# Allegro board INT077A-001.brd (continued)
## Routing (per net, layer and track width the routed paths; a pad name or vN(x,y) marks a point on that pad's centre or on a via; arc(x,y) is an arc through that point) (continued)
SCL_PD: length 2.8
  TOP w0.305: R47.2 99.03,62.23 98.2,63.07 SW2.12
SCL_PUP: length 2.2
  TOP w0.305: SW1.14 v1(95.81,52.91)
  BOTTOM w0.305: R4.1 v1(95.81,52.91)
SCL_SMBCLK: length 85.6
  TOP w0.305: J13.1 106.12,62.99 106.12,65.48 U2.6 94.03,74.37 92.79,73.13 92.79,53.95 91.72,52.88 90.55,52.88 90.53,52.91 SW1.3 88.7,52.91 88.67,52.88 78.49,52.88 75.15,49.55 U1.38 ; SW2.5 v1(90.78,63.07)
  BOTTOM w0.305: v1(90.78,63.07) 91.72,63.07 93.12,64.47 93.12,72.62 94.87,74.37 U2.6
SDA_PD: length 3
  TOP w0.305: SW2.11 98.15,61.8 98.69,61.25 99.14,61.25 99.69,60.7 R46.2
SDA_PUP: length 2.4
  TOP w0.305: SW1.13 v1(95.78,51.64)
  BOTTOM w0.305: R5.1 96.16,51.26 v1(95.78,51.64)
SDA_SMBDAT: length 85.3
  TOP w0.305: SW2.6 v1(90.88,61.8) ; U1.37 75.72,49.05 78.33,51.66 88.67,51.66 88.7,51.64 SW1.4 92.84,51.64 93.78,52.58 93.78,70.48 95.07,71.78 96.14,71.78 96.19,71.83 U2.5 ; J13.3 111.2,61.47 111.18,61.49 111.18,64.21 103.56,71.83 v1(101.85,71.83)
  BOTTOM w0.305: v1(101.85,71.83) U2.5 96.19,71.83 94.36,70 94.36,62.53 93.62,61.8 v1(90.88,61.8)
SMBUSZ: length 22.5
  TOP w0.305: U1.39 74.56,50.05 78.69,54.18 SW1.2
SMBUSZ_PD: length 2.1
  TOP w0.305: SW1.15 v1(95.91,54.18)
  BOTTOM w0.305: v1(95.91,54.18) 96.29,54.56 R24.2
TEST_PUP: length 2.6
  TOP w0.305: SW1.16 v1(95.78,55.45)
  BOTTOM w0.305: R22.1 96.55,56.21 v1(95.78,55.45)
TEST_TRSTZ: length 98.5
  TOP w0.305: v1(90.68,55.5) 89.66,55.5 SW1.1 89.59,55.42 v1(88.47,55.42) ; U1.49 67.25,56.36 67.66,56.77 v1(67.72,56.77)
  BOTTOM w0.305: v1(67.72,56.77) 84.56,56.77 85.9,55.42 v1(88.47,55.42) ; JP6.1 84.1,92.56 82.88,92.56 82.09,93.34 82.09,96.09 82.93,96.93 95.81,96.93 100.3,92.43 100.3,80.95 103.23,78.03 103.23,59.26 101.52,57.56 94.18,57.56 92.13,55.5 v1(90.68,55.5)
USB_DM_DN1: length 107.3
  TOP w0.229: U1.2 58.06,54.13 56.87,54.13 56.87,54.14 55.64,54.14 53.52,56.26 43.82,56.26 42.7,55.14 14.12,55.14 7.54,48.56 7.54,10.69 9.27,8.97 15.67,8.97 17.61,10.91 17.61,12.9 J4.2
USB_DM_DN2: length 71.3
  TOP w0.229: J3.2 48.09,12.9 48.09,10.5 46.25,8.66 39.67,8.66 37.95,10.39 37.95,43.54 43.01,48.6 51.37,48.6 52.92,50.14 56.54,50.14 56.63,50.05 U1.10
USB_DM_DN3: length 55.1
  TOP w0.229: U1.18 60.17,45.36 60.17,44.17 60.16,44.17 60.16,43.73 57.28,40.85 57.28,28.61 67.01,18.88 67.01,12.25 70.32,8.94 76.11,8.94 78.57,11.4 78.57,12.9 J5.2
USB_DM_DN4: length 78.7
  TOP w0.229: U1.25 63.67,45.36 63.67,44.17 63.67,44.17 63.67,40.04 64.94,38.77 64.94,33.8 71.23,27.51 91.5,27.51 99.36,19.64 99.36,8.93 100.64,7.65 107,7.65 109.05,9.7 109.05,12.9 J2.2
USB_DM_UP: length 40.5
  TOP w0.229: J1.2 65.57,87.2 70.18,87.2 71.91,85.47 71.91,77.72 65.61,71.42 65.61,60.35 64.84,59.58 64.84,57.43 64.83,57.43 64.83,56.24 U1.54
USB_DP_DN1: length 109
  TOP w0.229: U1.1 58.06,54.47 56.87,54.47 56.87,54.47 55.78,54.47 53.65,56.59 43.68,56.59 42.57,55.47 13.99,55.47 7.21,48.7 7.21,10.56 9.13,8.64 15.81,8.64 17.95,10.77 17.95,12.9 J4.3
USB_DP_DN2: length 73
  TOP w0.229: U1.9 56.63,50.55 56.54,50.47 52.78,50.47 51.24,48.93 42.87,48.93 37.62,43.67 37.62,10.25 39.54,8.33 46.39,8.33 48.43,10.37 48.43,12.9 J3.3
USB_DP_DN3: length 56.2
  TOP w0.229: U1.17 59.83,45.36 59.83,44.17 59.83,44.17 59.83,43.87 56.95,40.99 56.95,28.47 66.67,18.75 66.67,12.12 70.18,8.61 76.25,8.61 78.91,11.26 78.91,12.9 J5.3
USB_DP_DN4: length 79.8
  TOP w0.229: U1.24 63.33,45.36 63.33,44.17 63.33,44.17 63.33,39.91 64.61,38.63 64.61,33.66 71.09,27.18 91.36,27.18 99.03,19.51 99.03,8.79 100.51,7.32 107.14,7.32 109.39,9.56 109.39,12.9 J2.3
USB_DP_UP: length 41.1
  TOP w0.229: J1.3 65.56,87.53 70.32,87.53 72.24,85.61 72.24,77.59 65.94,71.29 65.94,60.21 65.17,59.44 65.17,56.24 U1.53
USB_SSRXM_DN1: length 64
  TOP w0.229: U1.7 56.63,51.55 56.54,51.64 51.26,51.64 50.38,50.75 37.96,50.75 20.94,33.74 20.94,18.4 21.62,17.73 21.62,17.27 20.94,16.6 20.94,16.08 J4.5
USB_SSRXM_DN2: length 38.7
  TOP w0.229: U1.15 58.06,47.63 56.87,47.63 56.87,47.64 56.13,47.64 52.63,44.14 52.63,41.33 54.36,39.6 54.36,29.84 51.42,26.91 51.42,18.32 52.1,17.65 52.1,17.21 51.42,16.54 51.42,16.08 J3.5
USB_SSRXM_DN3: length 47.1
  TOP w0.229: J5.5 81.9,16.08 81.9,23.1 79.58,25.43 66.35,25.43 61.75,30.03 61.75,41.2 62.67,42.12 62.67,45.36 U1.23
USB_SSRXM_DN4: length 66.7
  TOP w0.229: J2.5 112.38,16.08 112.38,25.56 105.23,32.72 76.29,32.72 66.17,42.83 66.17,45.36 U1.30
USB_SSRXN_UP: length 40.1
  TOP w0.229: U1.59 62.33,56.24 62.33,57.43 62.34,57.43 62.34,61.95 60.02,64.26 60.02,76.6 55.8,80.81 55.8,86.17 56.68,87.05 59.55,87.05 60.27,86.32 60.27,85.07 J1.8
USB_SSRXP_DN1: length 64
  TOP w0.229: J4.6 20.61,16.08 20.61,33.87 37.83,51.08 50.25,51.08 51.13,51.97 56.54,51.97 56.63,52.05 U1.6
USB_SSRXP_DN2: length 38.7
  TOP w0.229: J3.6 51.09,16.08 51.09,27.05 54.03,29.98 54.03,39.46 52.3,41.19 52.3,44.27 55.99,47.97 58.06,47.97 U1.14
USB_SSRXP_DN3: length 47.1
  TOP w0.229: J5.6 81.57,16.08 81.57,22.96 79.44,25.1 66.22,25.1 61.42,29.9 61.42,41.34 62.34,42.26 62.34,44.17 62.33,44.17 62.33,45.36 U1.22
USB_SSRXP_DN4: length 66.7
  TOP w0.229: U1.29 65.83,45.36 65.83,44.17 65.84,44.17 65.84,42.7 76.15,32.38 105.1,32.38 112.05,25.43 112.05,16.08 J2.6
USB_SSRXP_UP: length 40.1
  TOP w0.229: J1.9 59.54,84.36 59.94,84.77 59.94,86.18 59.41,86.72 59.05,86.72 58.72,86.39 58.72,86.21 58.4,85.88 57.93,85.88 57.61,86.21 57.61,86.39 57.28,86.72 56.82,86.72 56.13,86.03 56.13,80.95 60.35,76.73 60.35,64.4 62.67,62.08 62.67,56.24 U1.58
USB_SSTXM_DN1: length 64.1
  TOP w0.229: C52.2 14.94,22.13 14.94,34.14 33.93,53.14 44.09,53.14 44.98,54.03 53.44,54.03 54.33,53.14 56.87,53.14 56.87,53.13 58.06,53.13 U1.4
USB_SSTXM_DN2: length 38.1
  TOP w0.229: U1.12 58.06,49.13 56.87,49.13 56.87,49.14 54.89,49.14 52.36,46.61 48.97,46.61 43.36,41 43.36,34.62 45.42,32.56 45.42,22.13 C43.2
USB_SSTXM_DN3: length 36.5
  TOP w0.229: U1.20 61.17,45.36 61.17,43.94 61.16,43.93 61.16,42.52 59.69,41.05 59.69,29.27 65.62,23.34 75.23,23.34 76.05,22.53 C53.2
USB_SSTXM_DN4: length 57.2
  TOP w0.229: U1.27 64.67,45.36 64.67,41.73 67.82,38.58 67.82,35.01 72.7,30.12 100.59,30.12 106.38,24.34 106.38,22.13 C42.2
USB_SSTXM_UP: length 22.8
  TOP w0.229: U1.56 63.75,57.75 63.84,57.83 63.84,60.02 63.5,60.35 63.5,73.08 66.46,76.04 66.46,77.37 C36.2
USB_SSTXP_DN1: length 64.6
  TOP w0.229: U1.3 58.06,53.47 54.47,53.47 53.58,54.36 44.85,54.36 43.96,53.47 33.8,53.47 14.61,34.28 14.61,22.13 C54.2
USB_SSTXP_DN2: length 38.7
  TOP w0.229: C45.2 45.09,22.13 45.09,32.42 43.03,34.48 43.03,41.13 48.83,46.94 52.22,46.94 54.75,49.47 58.06,49.47 U1.11
USB_SSTXP_DN3: length 36.5
  TOP w0.229: C55.2 75.58,22.13 75.58,22.53 75.1,23.01 65.48,23.01 59.36,29.13 59.36,41.18 60.83,42.66 60.83,44.07 60.84,44.07 60.84,44.17 60.83,44.17 60.83,45.36 U1.19
USB_SSTXP_DN4: length 57.2
  TOP w0.229: C44.2 106.05,22.13 106.05,24.21 100.46,29.79 72.57,29.79 67.49,34.87 67.49,38.45 64.34,41.6 64.34,44.17 64.33,44.17 64.33,45.36 U1.26
USB_SSTXP_UP: length 22.8
  TOP w0.229: U1.55 64.25,57.75 64.17,57.83 64.17,60.15 63.83,60.49 63.83,72.94 66.79,75.9 66.79,77.37 C37.2
USB_VBUS_UP: length 8.7
  TOP w0.305: D1.1 v1(48.92,85.22) ; C35.1 v1(51.74,85.04)
  L3_VCC w0.305: J1.1 63.24,86.36 ; J1.1 62.23,85.35 ; J1.1 61.22,86.36 ; J8.2 77.85,81.03 ; J8.2 76.78,79.96 ; J8.2 77.85,78.89
N17052812: length 25
  TOP w0.305: U1.48 68.85,56.33 69.34,56.82 69.34,66.6 73.91,71.17 R3.1 R2.1
N17181221: length 4.6
  TOP w0.305: R14.1 99.82,75.93 99.82,75.93 R10.2 U2.7
N17181233: length 2.6
  TOP w0.305: R11.2 87.66,79.48 87.68,79.45 U2.1
N17181243: length 2.6
  TOP w0.305: U2.2 87.68,76.91 87.66,76.94 R12.2
N17181324: length 2.6
  TOP w0.305: U2.3 87.68,74.37 87.66,74.4 R13.2
N17381185: length 1.8
  TOP w0.305: v1(17.98,24.38) D5.2
  BOTTOM w0.305: R30.1 v1(17.98,24.38)
N17383170: length 2.1
  TOP w0.305: D1.2 R16.1
N17408350: length 2.4
  TOP w0.305: D4.2 R28.1
N18334081: length 11.6
  TOP w0.305: U1.62 60.75,57.59 v1(60.48,57.86)
  BOTTOM w0.305: Y1.3 58.03,64.58 57.71,64.26 57.71,60.68 57.99,60.4 C2.1 59.08,60.25 59.08,59.69 60.07,58.7 R1.2 60.48,58.57 v1(60.48,57.86)
N18334093: length 7.4
  TOP w0.305: v1(61.54,57.86) 61.25,57.57 U1.61
  BOTTOM w0.305: v1(61.54,57.86) 61.54,58.6 R1.1 62.61,58.7 63.14,59.23 63.14,59.65 63.17,59.67 C1.1 Y1.1
N18711690: length 2
  TOP w0.305: D6.2 48.26,23.46 v1(48.26,24.36)
  BOTTOM w0.305: R31.1 v1(48.26,24.36)
N18712170: length 2.1
  TOP w0.305: v1(79.81,23.29) 78.87,23.29 D7.2
  BOTTOM w0.305: R35.1 78.88,22.95 79.46,22.95 v1(79.81,23.29)
N18712674: length 1.9
  TOP w0.305: D8.2 v1(109.5,24.31)
  BOTTOM w0.305: v1(109.5,24.31) R37.1
N18713919: length 1.9
  TOP w0.305: U1.64 v1(59.24,56.15)
  BOTTOM w0.305: R21.2 58.36,56.92 58.79,56.5 58.89,56.5 v1(59.24,56.15)
N18725733: length 2.6
  TOP w0.305: R2.2 J8.1
N18726136: length 10.4
  BOTTOM w1.016: J7.1 86.94,40.34 84.87,40.34 79.86,45.35 FB1.2
N18726182: length 17.1
  BOTTOM w1.016: FB2.2 47.52,50.34 J9.1
N18744223: length 14.5
  TOP w0.813: 109.12,75.3 SW3.1 ; SW3.1 110.82,77 ; SW3.1 110.82,73.59 ; 109.32,82.67 J6.1 ; J6.1 106.98,85.01 ; J6.1 111.66,85.01 ; J6.1 109.32,87.35
N187210031: length 3.2
  TOP w0.305: D2.2 v1(83.46,67.49)
  BOTTOM w0.305: v1(83.46,67.49) 83.46,68.48 83.46,68.49 R41.2
N187210111: length 3.1
  TOP w0.305: D3.2 v1(83.46,73.25)
  BOTTOM w0.305: v1(83.46,73.25) 83.46,74.02 83.46,74.02 R40.2

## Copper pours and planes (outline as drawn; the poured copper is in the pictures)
GND on TOP: 1.27,1.27 1.27,97.79 127,97.79 127,1.27 ; 1 cut-out
GND on BOTTOM: 1.27,1.27 1.27,97.79 127,97.79 127,1.27
GND on L2_GND: 1.27,1.27 1.27,97.79 127,97.79 127,1.27 ; 4 cut-outs
GND_EARTH on BOTTOM: 1.27,1.27 1.27,23.37 1.27,23.37 1.27,97.79 74.93,97.79 74.93,87.63 8.89,87.63 8.89,12.6 21.95,12.6 23.32,13.97 25.96,13.97 26.59,13.33 32.44,13.33 33.17,12.6 52.25,12.6 53.8,14.15 56.21,14.15 57.02,13.33 63.12,13.33 63.86,12.6 82.85,12.6 84.43,14.17 86.64,14.17 87.45,13.36 94.34,13.36 95.1,12.6 113.59,12.6 115.21,14.22 116.89,14.22 116.89,17.5 127.02,17.5 127,1.27 ; 4 cut-outs
VDD11 on BOTTOM: 55.93,55.78 55.93,45.06 58.57,45.06 58.57,55.78
VDD11 on L3_VCC: 54.71,43.13 54.71,44.37 54.66,44.37 54.66,60.17 78.33,60.17 78.33,54.2 66.7,54.2 66.7,55.42 63.6,55.42 63.6,54.36 62.48,54.36 62.48,55.6 59.33,55.6 59.33,53.21 59.84,53.21 59.84,48.36 58.83,48.36 58.83,46 61.44,46 61.44,47.19 65.81,47.19 65.81,45.36 68.94,45.36 68.94,43.15 65.81,43.15 65.81,43.13
VDD33 on BOTTOM: 78.66,44.42 78.66,48.87 76.07,48.87 76.07,44.42
VDD33 on L3_VCC: 66.47,46.1 66.47,47.68 61.16,47.68 61.16,46.61 59.23,46.61 59.23,47.85 60.35,47.85 60.35,53.62 59.94,53.62 59.94,54.97 61.85,54.97 61.85,53.82 64.11,53.82 64.11,55.04 66.19,55.04 66.19,53.8 78.66,53.8 78.66,44.45 69.6,44.45 69.62,44.48 69.62,46.1 ; 1 cut-out
BOARD_1P1V on TOP: 34.21,73.46 34.21,69.72 34.01,69.52 34.01,68 31.47,68 31.45,67.97 31.45,66.73 29.74,66.73 29.72,66.75 29.67,66.75 29.18,66.27 25.6,66.27 25.55,66.32 25.55,73.43 25.58,73.46
BOARD_1P1V on L3_VCC: 39.01,44.48 39.01,65.51 26.44,65.51 26.44,72.16 46.1,72.16 46.1,69.47 53.64,69.47 53.64,44.48 ; 1 cut-out
BOARD_3P3V on TOP: 30.3,64.57 31.39,64.57 31.45,64.62 31.45,63.35 31.42,63.32 31.45,63.3 36.17,63.3 36.2,63.32 36.2,64.52 37.97,64.52 37.97,57.91 37.95,57.89 32.03,57.89 32.03,62.15 32.08,62.2 32.03,62.26 30.28,62.26 30.28,64.54
BOARD_3P3V on TOP: 112.34,50.01 112.34,56.29 112.17,56.46 101.78,56.46 101.73,56.41 101.73,51.79 101.96,51.56 104.67,51.56 104.98,51.26 107.04,51.26 107.09,51.31 107.14,51.31 108.46,49.99 112.32,49.99
BOARD_3P3V on L3_VCC: 2.01,21.59 2.01,97.79 45.54,97.79 45.54,73.76 24.66,73.76 24.66,64.52 37.57,64.52 37.57,42.42 79.35,42.42 79.35,97.79 102.03,97.79 102.03,63.2 112.19,63.2 112.19,41.07 120.42,41.07 120.42,21.59 ; 2 cut-outs
BOARD_5V on TOP: 114.73,50.04 114.73,54.89 114.33,55.3 114.33,59.16 121.77,59.16 121.77,58.65 121.74,58.62 121.74,50.52 121.26,50.04
BOARD_5V on L3_VCC: 2.08,1.27 2.08,20.32 121.84,20.32 121.84,41.86 114.33,41.86 114.15,41.68 114.15,64.85 105.13,64.85 104.98,65 104.98,97.79 126.82,97.79 126.82,1.27 ; 4 cut-outs
DN1_VBUS on TOP: 26.8,22.78 26.8,25.02 24.54,25.02 24.54,22.78
DN1_VBUS on BOTTOM: 11.25,18.47 11.25,24.74 14.86,24.74 14.86,22.17 19.84,22.17 19.84,24.99 26.82,24.99 26.82,22.78 21.41,22.78 21.41,18.47
DN2_VBUS on TOP: 57.71,22.81 57.71,24.97 55.32,24.97 55.32,22.81
DN2_VBUS on BOTTOM: 41.63,18.47 41.63,24.74 45.24,24.74 45.24,22.17 50.22,22.17 50.22,24.99 57.68,24.99 57.68,22.78 51.79,22.78 51.79,18.47
DN3_VBUS on TOP: 88.27,22.73 88.27,24.89 85.47,24.89 85.47,22.73
DN3_VBUS on BOTTOM: 72.11,18.39 72.11,24.66 75.72,24.66 75.72,22.1 80.7,22.1 80.7,24.92 88.21,24.92 88.21,22.71 82.27,22.71 82.27,18.39
DN4_VBUS on TOP: 118.9,22.81 118.9,25.04 116.31,25.04 116.31,22.81
DN4_VBUS on BOTTOM: 102.77,18.47 102.77,24.74 106.38,24.74 106.38,22.17 111.35,22.17 111.35,24.99 118.97,24.99 118.97,22.78 112.93,22.78 112.93,18.47
Net_10 on TOP (solid shape): 13.99,79.46 13.02,79.45 13.5,82.75 14.47,82.76
Net_10 on TOP (solid shape): 14.32,84.34 14.49,84.22 14.61,84.04 14.65,83.84 14.59,83.6 14.49,83.44 14.3,83.31 14.1,83.28 13.88,83.32 13.71,83.43 13.58,83.62 13.54,83.83 13.59,84.06 13.69,84.21 13.89,84.35 14.1,84.38
Net_10 on TOP (solid shape): 11.99,85.94 11.99,84.05 12.13,83.36 12.35,83.04 12.72,82.88 13.29,82.9 13.15,81.89 12.63,81.89 12.5,81.04 13.02,81.04 12.77,79.17 12.77,79.01 12.84,78.83 13.03,78.59 13.17,78.49 13.4,78.39 13.69,78.31 14.11,78.27 14.47,78.31 14.61,78.38 14.65,78.45 14.65,78.97 14.49,78.99 14.28,79.03 14.21,79.09 14.17,79.21 14.44,81.04 14.99,81.04 15.13,81.88 14.6,81.9 14.78,82.97 15.01,83.05 15.67,83.1 16.37,82.98 16.73,82.74 17.3,82.64 17.28,81.46 17.45,81.04 17.58,80.46 17.66,79.54 17.58,78.48 17.49,78.17 17.35,78.01 17.08,77.89 16.28,77.69 15.7,77.41 14.55,76.97 13.85,76.42 13.3,75.78 13.07,75 13.11,74.46 13.19,74.05 13.39,73.46 13.39,73.29 12.95,73.39 12.48,73.44 12.08,73.74 11.87,73.81 11.66,74.17 10.88,75.79 10.56,76.42 10.1,77.53 9.76,78.02 9.5,78.16 9.14,78.15 8.71,77.91 8.56,77.78 8.25,77.71 8.03,77.77 7.76,78.07 7.35,78.55 7.02,79.08 6.63,79.54 6.22,79.96 5.74,80.15 5.54,80.32 5.47,80.5 5.36,80.68 9.14,80.68 9.14,85.95
USB_VBUS_UP on L3_VCC: 54.66,61.09 54.66,71.12 47.57,71.12 47.57,97.79 78.31,97.79 78.31,61.09
N18744223 on TOP: 108.28,88.19 106.45,86.36 106.45,75.54 109.12,72.87 111.18,72.87 112.45,74.14 112.45,86.84 111.1,88.19

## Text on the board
Ref Des/Silkscreen Bottom: FOR EVALUATION ONLY : | NOT FCC APPROVED FOR RESALE
Ref Des/Silkscreen Top: AUTOENZ_PD / BB_bmConfig1_PD | GANGED_PU / BB_CONNECT_PU | PWRCTL_POL_PD | FULLPWRMGMTZ_PU/BB_bmConfig0_PU | SCL_PD | SDA_PD | AUTOENZ_PU / BB_bmConfig1_PU | N/A | TEST_PUP | SCL_PUP | SDA_PUP | BATEN0 | BATEN1 | SMBUSZ_PD | BATEN2 | BATEN3 | BOARD | 1P1V | VBUS | USB | UP | 3P3V | SW2 | SW1 | Pb | GND | SCL | SDA | PORT1 | PORT2 | PORT3 | PORT4 | LB1 | 5VDC | ONLY
PAGE_OUTLINE: 4. BOARDS MUST MEET OR EXCEED UL94-V0 REQUIREMENT | GENERAL NOTES. UNLESS OTHERWISE SPECIFIED | 1.  ALL FABRICATION ITEMS MUST MEET OR EXCEED BEST | INDUSTRY PRACTICE : IPC-A-600C (Commercial std.) | 2.  LAMINATE MATERIAL  :  FR4 POLYCLAD 370 or EQUIVALENT | 3.  COPPER WEIGHT  : 2oz START INTERNAL, 1oz START EXTERNAL | 4.  FINISHED BOARD THICKNESS :  .062  +/- 10% | 5.  MAXIMUM WARP AND TWIST TO BE :  .005 INCH PER INCH | 6.  MINIMUM COPPER WALL THICKNESS OF PLATED-THRU | HOLES TO BE .001 INCH. THERE MUST BE 1MIL OR GREATER PLATING ON | EACH SIDE OF THE BARREL WHEN VIEWED IN THE CROSS SECTION | 7.  MINIMUM ANNULAR RING OF PLATED-THRU HOLES | TO BE .002 INCH | 8.  MAXIMUM ALLOWABLE LINE REDUCTION TO BE | 20% OR .002 WHICHEVER IS SMALLER | 9.  0.009 SIGNAL LINES ON LAYER 1 TO BE | IMPEDANCE CONTROLLED 90 OHMS DIFFERENTIAL +/- 10% | 11. DIELECTRIC CONSTANTS ARE         CORE : 4.1 | PREPREG : 4.1 | 13. A CROSS SECTION MOUNT AND DIGITAL PHOTO'S OF VIA'S TO BE PROVIDED | 14. USE THE (DRPP) DUTCH REVERSE PLATING PROCESS | PROCESS NOTES | 1. CIRCUITRY ON OUTER LAYERS TO BE PLATED WITH : NICKEL GOLD | 2. SOLDERMASK BOTH SIDES PER ARTWORK  :  BLACK LPI | 3. SILKSCREEN BOTH SIDES PER ARTWORK  :  COLOR = WHITE
DEVICE_TYPE_TOP: 5 mil | 25mil | 1 | 2 | 3 | 4 | TOP | L2_GND | L3_VCC | BOTTOM
TOLERANCE_TOP: FIGURE | SIZE | 160.0 | 140.0 | 120.0 | 91.0 | 65.0 | 52.0 | 40.0 | 37.0 | 36.0 | 35.0 | 28.0 | 12.0 | 8.0 | 125.2 | 61.0 | DRILL CHART: TOP to BOTTOM | ALL UNITS ARE IN MILS | TOLERANCE | +3.0/-3.0 | +3.0/-12.0 | PLATED | NON-PLATED | QTY | 4 | 1 | 2 | 10 | 6 | 8 | 41 | 51 | 531
